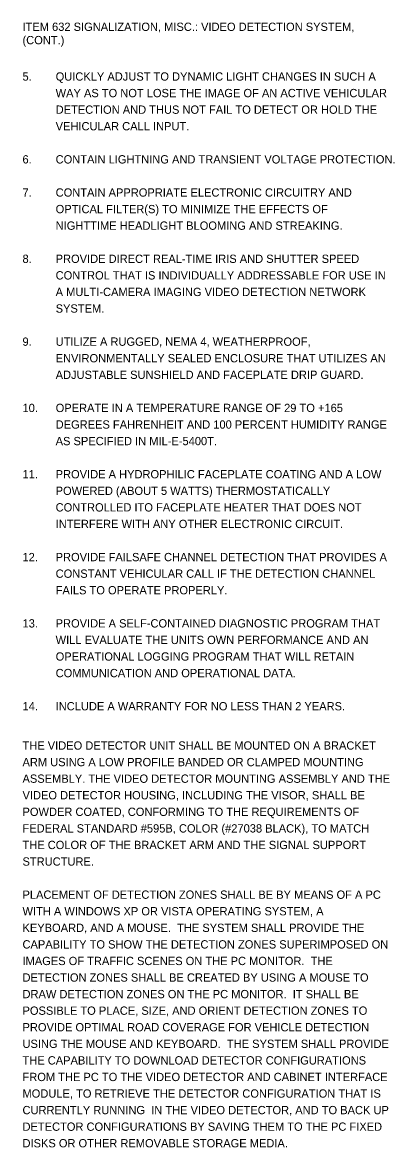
# Model space of a CAD drawing. Extents: x -38 to 65, y -51 to 25.
# Drawn here: x 0.66 to 6.95, y -49.53 to -30.52 of the extents above; entities that cross this region are included whole.
import ezdxf

# ---------------------------------------------------------------- set-up
doc = ezdxf.new("R2010")
doc.units = 0
doc.layers.add('SH_Data', color=7, linetype='Continuous')
doc.layers.add('SH_Text', color=7, linetype='Continuous')

msp = doc.modelspace()

# ---------------------------------------------------------------- texts
at = {"layer": 'SH_Data'}
for s, p in [('ITEM 632 SIGNALIZATION, MISC.: VIDEO DETECTION SYSTEM, ', (0.662, -30.667)), ('(CONT.)', (0.662, -30.892))]:
    msp.add_text(s, height=0.14, rotation=360, dxfattribs=at).set_placement(p)
at = {"layer": 'SH_Text'}
for s, p in [('5.', (0.662, -31.507)), ('QUICKLY ADJUST TO DYNAMIC LIGHT CHANGES IN SUCH A ', (1.222, -31.507)), ('WAY AS TO NOT LOSE THE IMAGE OF AN ACTIVE VEHICULAR ', (1.222, -31.787)), ('DETECTION AND THUS NOT FAIL TO DETECT OR HOLD THE ', (1.222, -32.067)), ('VEHICULAR CALL INPUT.', (1.222, -32.347)), ('6.', (0.662, -32.907)), ('CONTAIN LIGHTNING AND TRANSIENT VOLTAGE PROTECTION.', (1.222, -32.907)), ('7.', (0.662, -33.467)), ('CONTAIN APPROPRIATE ELECTRONIC CIRCUITRY AND ', (1.222, -33.467)), ('OPTICAL FILTER(S) TO MINIMIZE THE EFFECTS OF ', (1.222, -33.747)), ('NIGHTTIME HEADLIGHT BLOOMING AND STREAKING.', (1.222, -34.027)), ('8.', (0.662, -34.587)), ('PROVIDE DIRECT REAL-TIME IRIS AND SHUTTER SPEED ', (1.222, -34.587)), ('CONTROL THAT IS INDIVIDUALLY ADDRESSABLE FOR USE IN ', (1.222, -34.867)), ('A MULTI-CAMERA IMAGING VIDEO DETECTION NETWORK ', (1.222, -35.147)), ('SYSTEM.', (1.222, -35.427)), ('9.', (0.662, -35.987)), ('UTILIZE A RUGGED, NEMA 4, WEATHERPROOF, ', (1.222, -35.987)), ('ENVIRONMENTALLY SEALED ENCLOSURE THAT UTILIZES AN ', (1.222, -36.267)), ('ADJUSTABLE SUNSHIELD AND FACEPLATE DRIP GUARD.', (1.222, -36.547)), ('10.', (0.662, -37.107)), ('OPERATE IN A TEMPERATURE RANGE OF 29 TO +165 ', (1.222, -37.107)), ('DEGREES FAHRENHEIT AND 100 PERCENT HUMIDITY RANGE ', (1.222, -37.387)), ('AS SPECIFIED IN MIL-E-5400T.', (1.222, -37.667)), ('11.', (0.662, -38.227)), ('PROVIDE A HYDROPHILIC FACEPLATE COATING AND A LOW ', (1.222, -38.227)), ('POWERED (ABOUT 5 WATTS) THERMOSTATICALLY ', (1.222, -38.507)), ('CONTROLLED ITO FACEPLATE HEATER THAT DOES NOT ', (1.222, -38.787)), ('INTERFERE WITH ANY OTHER ELECTRONIC CIRCUIT.', (1.222, -39.067)), ('12.', (0.662, -39.627)), ('PROVIDE FAILSAFE CHANNEL DETECTION THAT PROVIDES A ', (1.222, -39.627)), ('CONSTANT VEHICULAR CALL IF THE DETECTION CHANNEL ', (1.222, -39.907)), ('FAILS TO OPERATE PROPERLY.', (1.222, -40.187)), ('13.', (0.662, -40.747)), ('PROVIDE A SELF-CONTAINED DIAGNOSTIC PROGRAM THAT ', (1.222, -40.747)), ('WILL EVALUATE THE UNITS OWN PERFORMANCE AND AN ', (1.222, -41.027)), ('OPERATIONAL LOGGING PROGRAM THAT WILL RETAIN ', (1.222, -41.307)), ('COMMUNICATION AND OPERATIONAL DATA.', (1.222, -41.587)), ('14.', (0.662, -42.147)), ('INCLUDE A WARRANTY FOR NO LESS THAN 2 YEARS.', (1.222, -42.147)), ('THE VIDEO DETECTOR UNIT SHALL BE MOUNTED ON A BRACKET ', (0.662, -42.811)), ('ARM USING A LOW PROFILE BANDED OR CLAMPED MOUNTING ', (0.662, -43.091)), ('ASSEMBLY. THE VIDEO DETECTOR MOUNTING ASSEMBLY AND THE ', (0.662, -43.371)), ('VIDEO DETECTOR HOUSING, INCLUDING THE VISOR, SHALL BE ', (0.662, -43.651)), ('POWDER COATED, CONFORMING TO THE REQUIREMENTS OF ', (0.662, -43.931)), ('FEDERAL STANDARD #595B, COLOR (#27038 BLACK), TO MATCH ', (0.662, -44.211)), ('THE COLOR OF THE BRACKET ARM AND THE SIGNAL SUPPORT ', (0.662, -44.491)), ('STRUCTURE.', (0.662, -44.771)), ('PLACEMENT OF DETECTION ZONES SHALL BE BY MEANS OF A PC ', (0.662, -45.331)), ('WITH A WINDOWS XP OR VISTA OPERATING SYSTEM, A ', (0.662, -45.611)), ('KEYBOARD, AND A MOUSE.  THE SYSTEM SHALL PROVIDE THE ', (0.662, -45.891)), ('CAPABILITY TO SHOW THE DETECTION ZONES SUPERIMPOSED ON ', (0.662, -46.171)), ('IMAGES OF TRAFFIC SCENES ON THE PC MONITOR.  THE ', (0.662, -46.451)), ('DETECTION ZONES SHALL BE CREATED BY USING A MOUSE TO ', (0.662, -46.731)), ('DRAW DETECTION ZONES ON THE PC MONITOR.  IT SHALL BE ', (0.662, -47.011)), ('POSSIBLE TO PLACE, SIZE, AND ORIENT DETECTION ZONES TO ', (0.662, -47.291)), ('PROVIDE OPTIMAL ROAD COVERAGE FOR VEHICLE DETECTION ', (0.662, -47.571)), ('USING THE MOUSE AND KEYBOARD.  THE SYSTEM SHALL PROVIDE ', (0.662, -47.851)), ('THE CAPABILITY TO DOWNLOAD DETECTOR CONFIGURATIONS ', (0.662, -48.131)), ('FROM THE PC TO THE VIDEO DETECTOR AND CABINET INTERFACE ', (0.662, -48.411)), ('MODULE, TO RETRIEVE THE DETECTOR CONFIGURATION THAT IS ', (0.662, -48.691)), ('CURRENTLY RUNNING  IN THE VIDEO DETECTOR, AND TO BACK UP ', (0.662, -48.971)), ('DETECTOR CONFIGURATIONS BY SAVING THEM TO THE PC FIXED ', (0.662, -49.251)), ('DISKS OR OTHER REMOVABLE STORAGE MEDIA. ', (0.662, -49.531))]:
    msp.add_text(s, height=0.14, rotation=360, dxfattribs=at).set_placement(p)

doc.saveas('drawing.dxf')
